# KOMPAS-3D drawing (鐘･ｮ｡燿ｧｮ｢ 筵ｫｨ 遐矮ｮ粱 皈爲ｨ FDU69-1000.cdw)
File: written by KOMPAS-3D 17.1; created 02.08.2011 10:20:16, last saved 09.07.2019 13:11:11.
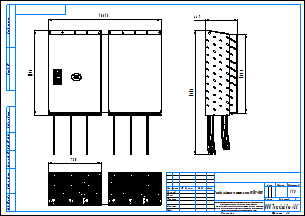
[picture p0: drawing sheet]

Title block, sheet 1: name: Преобразователи частоты серии FDU69-1000; scale: 1:10; sheets: 1; sheet format: A3; stored path: \\adlc.lan\data\АДЛ_ПКД\3D-модели\Поставщики\Оборудование Emotron\Преобразователи частоты\Серия FDU 2.0\KOMPAS 2D\Преобразователи частоты серии FDU69-1000.cdw

Views: Спереди 1
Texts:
  Рама для чертежей
  Лит-Масса-Масштаб
  Материал-Предприятие
  Масштаб
  Изм.
  Лист
  № докум.
  Подп.
  Дата
  Лит.
  Разраб.
  Пров.
  Т.контр.
  Листов
  Внимание! Данный продукт является объектом авторского права ООО «Торговый Дом АДЛ».
  Запрещается изменение, копирование, распространение
  (в том числе путем копирования на другие сайты и ресурсы в Интернете)
  или любое иное использование информации и объектов без предварительного
  согласия правообладателя (ООО «Торговый Дом АДЛ»).
  Н.контр.
  Утв.
  ООО "Торговый дом АДЛ"
  Изменение
  Номер документа
  Подпись
  Обозначение документа
  Наименование изделия
  Масса изделия по ГОСТ 2.109-73
  Порядковый номер листа
  Общее количество листов в документе
  Характер работы, выполненной лицом, подписавшим документ
  Наименование или индекс предприятия, выпускающего документ
  Инв. № подл.
  Подп. и дата
  Взам. инв. №
  Инв. № дубл.
  Инвентарный номер подлинника по ГОСТ 2.501-68
  Подпись принявшего подлинник в отдел технической документации
  Инвентарный номер подлинника, взамен которого выпущен данный подлинник
  Инвентарный номер дубликата по ГОСТ 2.502-68
  Подпись принявшего дубликат в отдел технической документации
  Справ. №
  Перв. примен.
  Обозначение документа, взамен или на основании которого выпущен данный документ
  Обозначение документа, в котором впервые записан данный документ
  Подпись лица, копировавшего чертеж
  Обозначение формата листа
  !Рама для чертежа
Dimensions and other numbers on the sheet: 1561,5; 1176; 730; 1718; 1096; 449; 1:10; 1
